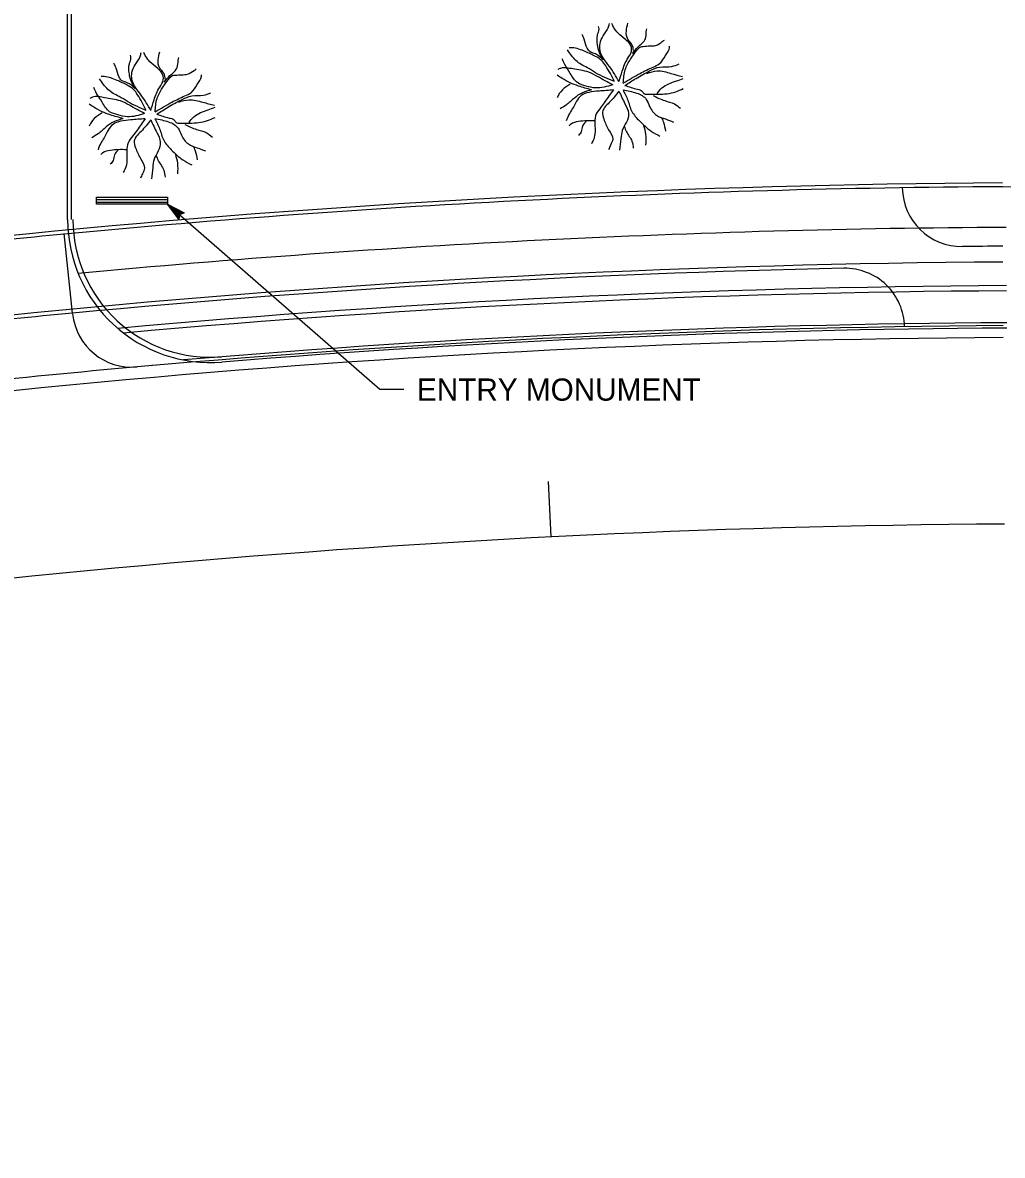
# Model space of a CAD drawing. Extents: x 6711323 to 6714641, y 1869258 to 1871224.
# Drawn here: x 6712585.3 to 6712708.8, y 1869509.9 to 1869652.6 of the extents above; entities that cross this region are included whole.
import ezdxf

# ---------------------------------------------------------------- set-up
doc = ezdxf.new("R2010")
doc.units = 0
for name, color, linetype in [('49 Planting', 7, 'Continuous'), ('Curb Gutter (21)', 7, 'Continuous'), ('Level 11', 7, 'Continuous'), ('Level 13', 7, 'Continuous'), ('Level 14', 7, 'Continuous'), ('Level 21', 7, 'Continuous'), ('Level 46', 7, 'Continuous'), ('Level 60', 7, 'Continuous'), ('Profile Grid (9)', 7, 'Continuous')]:
    doc.layers.add(name, color=color, linetype=linetype)

msp = doc.modelspace()

# ---------------------------------------------------------------- linework, layer by layer
at = {"layer": '49 Planting'}
for p, q in [((6712594.64, 1869629.99), (6712603.58, 1869629.99)), ((6712594.67, 1869630.32), (6712603.61, 1869630.32)), ((6712603.58, 1869629.74), (6712630.32, 1869606.44)), ((6712603.58, 1869629.74), (6712603.58, 1869629.74)), ((6712605.64, 1869628.63), (6712605.64, 1869628.63)), ((6712604.98, 1869627.86), (6712604.98, 1869627.86)), ((6712630.32, 1869606.44), (6712633.33, 1869606.44))]:
    msp.add_line(p, q, dxfattribs=at)
for points in [[(6712594.61, 1869630.62), (6712603.58, 1869630.62), (6712603.58, 1869629.74), (6712594.61, 1869629.74)], [(6712604.98, 1869627.86), (6712603.58, 1869629.74), (6712605.64, 1869628.63), (6712605.49, 1869628.58), (6712603.98, 1869629.39), (6712605.01, 1869628.01), (6712605.03, 1869628.17), (6712604.38, 1869629.05), (6712605.34, 1869628.53), (6712605.19, 1869628.48), (6712604.78, 1869628.71), (6712605.06, 1869628.32), (6712605.08, 1869628.45), (6712605.64, 1869628.63), (6712605.08, 1869628.45)]]:
    msp.add_lwpolyline(points, close=True, dxfattribs=at)
at = {"layer": 'Curb Gutter (21)'}
for p, q in [((6712590.97, 1869627.79), (6712590.97, 1869684.57)), ((6712591.47, 1869627.79), (6712591.47, 1869684.57))]:
    msp.add_line(p, q, dxfattribs=at)
for radius, start, end in [(18, 180, 184.1364), (17.33, 180.0001, 184.0883)]:
    msp.add_arc((6712608.97, 1869627.79), radius, start, end, dxfattribs=at)
at = {"layer": 'Level 11'}
for p, q in [((6712708.78, 1869631.94), (6712900.92, 1869633.18)), ((6712591.59, 1869616.01), (6712590.52, 1869626.04))]:
    msp.add_line(p, q, dxfattribs=at)
for centre, radius, start, end in [((6712717.46, 1868289.47), 1342.98, 90.36981, 110.14927), ((6712717.45, 1868289.47), 1342.5, 90.36992, 95.42473), ((6712703.67, 1869631.9), 7.5, 180.9083, 270.5882), ((6712717.45, 1868289.47), 1342.5, 95.42463, 96.70501), ((6712717.45, 1868289.47), 1335, 90.36992, 90.58819), ((6712717.46, 1868289.47), 1333, 90.36981, 110.14927), ((6712717.45, 1868289.47), 1332.5, 91.2326, 95.41993), ((6712688.95, 1869614.16), 7.5, 0.9083, 91.2326), ((6712717.45, 1868289.47), 1332.5, 95.41982, 96.70981), ((6712599.06, 1869616.7), 7.5, 186.0649, 275.0974), ((6712717.45, 1868289.47), 1325, 90.36992, 95.0974), ((6712717.45, 1868289.47), 1323.5, 90.36992, 110.14901)]:
    msp.add_arc(centre, radius, start, end, dxfattribs=at)
at = {"layer": 'Level 13'}
for centre, radius, start, end in [((6712717.45, 1868289.47), 1342.5, 90.36992, 95.42473), ((6712703.67, 1869631.9), 7.5, 180.9083, 270.5882), ((6712717.45, 1868289.47), 1335, 90.36992, 90.58819), ((6712717.45, 1868289.47), 1332.5, 91.2326, 95.41993), ((6712688.95, 1869614.16), 7.5, 0.9083, 91.2326), ((6712717.45, 1868289.47), 1325, 90.36992, 95.0974), ((6712717.45, 1868289.47), 1300, 90.36992, 110.14901)]:
    msp.add_arc(centre, radius, start, end, dxfattribs=at)
at = {"layer": 'Level 14'}
msp.add_lwpolyline([(6712651.52, 1869594.8), (6712651.87, 1869587.81)], dxfattribs=at)
at = {"layer": 'Level 21'}
msp.add_line((6712708.78, 1869631.94), (6712899.57, 1869633.17), dxfattribs=at)
for radius, start, end in [(1342.5, 95.42463, 96.70501), (1323.5, 90.36992, 110.14901), (1325, 95.0974, 97.03244), (1325, 95.01287, 95.01675)]:
    msp.add_arc((6712717.45, 1868289.47), radius, start, end, dxfattribs=at)
at = {"layer": 'Level 46'}
for centre, radius, start, end in [((6712608.97, 1869627.79), 18, 180, 274.6237), ((6712608.97, 1869627.79), 17.33, 180, 274.6237), ((6712716.96, 1868292.52), 1334.32, 90.33043, 95.36073), ((6712716.96, 1868292.52), 1326.98, 90.33043, 95.17418), ((6712716.96, 1868292.52), 1326.32, 90.33043, 95.14447), ((6712716.96, 1868292.52), 1322.3, 90.33043, 94.83264), ((6712716.96, 1868292.52), 1321.63, 90.33043, 94.6237)]:
    msp.add_arc(centre, radius, start, end, dxfattribs=at)
at = {"layer": 'Level 60'}
msp.add_line((6712591.59, 1869616.01), (6712590.52, 1869626.04), dxfattribs=at)
msp.add_arc((6712599.06, 1869616.7), 7.5, 186.0649, 275.0974, dxfattribs=at)
at = {"layer": 'Profile Grid (9)'}
for points in [[(6712660.48, 1869645.18), (6712659.25, 1869647.1), (6712658.08, 1869649.08), (6712658.08, 1869649.98), (6712658.47, 1869650.93), (6712659.12, 1869651.95), (6712659.25, 1869652.49)], [(6712660.48, 1869645.18), (6712660.87, 1869646.5), (6712661.58, 1869648.12), (6712662.04, 1869649.02), (6712661.84, 1869649.92), (6712661.32, 1869650.45), (6712660.35, 1869651.29), (6712659.83, 1869651.95), (6712659.57, 1869652.49)], [(6712662.29, 1869649.08), (6712662.1, 1869649.86), (6712661.97, 1869650.04), (6712661.58, 1869650.52), (6712661.39, 1869651.53), (6712661.58, 1869652.55)], [(6712658.47, 1869647.94), (6712657.5, 1869648.66), (6712656.79, 1869648.96), (6712656.46, 1869649.38), (6712656.07, 1869650.52), (6712655.82, 1869651.11)], [(6712658.47, 1869647.94), (6712657.95, 1869648.96), (6712657.76, 1869649.8), (6712657.76, 1869651.05), (6712657.95, 1869651.77), (6712657.89, 1869652.13)], [(6712662.17, 1869648.72), (6712662.88, 1869649.56), (6712663.79, 1869650.57), (6712663.91, 1869651.47), (6712663.98, 1869651.83)], [(6712661, 1869645), (6712661.26, 1869646.68), (6712661.91, 1869648), (6712662.68, 1869649.08), (6712663.2, 1869649.56), (6712663.53, 1869649.62), (6712664.37, 1869649.68), (6712665.08, 1869649.74), (6712665.92, 1869650.22), (6712666.18, 1869650.4)], [(6712661, 1869645), (6712663.12, 1869646.21), (6712664.76, 1869647.01), (6712665.54, 1869647.41), (6712666.32, 1869648.45), (6712666.83, 1869649.49), (6712666.83, 1869649.65)], [(6712599.47, 1869644.31), (6712598.95, 1869645.33), (6712598.75, 1869646.17), (6712598.75, 1869647.43), (6712598.95, 1869648.15), (6712598.88, 1869648.51)], [(6712601.47, 1869641.55), (6712600.24, 1869643.47), (6712599.08, 1869645.45), (6712599.08, 1869646.35), (6712599.47, 1869647.31), (6712600.11, 1869648.33), (6712600.24, 1869648.86)], [(6712601.47, 1869641.55), (6712601.86, 1869642.87), (6712602.58, 1869644.49), (6712603.03, 1869645.39), (6712602.84, 1869646.29), (6712602.32, 1869646.83), (6712601.35, 1869647.67), (6712600.83, 1869648.33), (6712600.57, 1869648.86)], [(6712603.29, 1869645.45), (6712603.09, 1869646.23), (6712602.97, 1869646.41), (6712602.58, 1869646.89), (6712602.38, 1869647.91), (6712602.58, 1869648.92)], [(6712603.16, 1869645.09), (6712603.87, 1869645.93), (6712604.78, 1869646.95), (6712604.91, 1869647.85), (6712604.97, 1869648.21)], [(6712659.9, 1869645.18), (6712657.51, 1869646.29), (6712656.48, 1869646.93), (6712655.7, 1869647.33), (6712654.49, 1869648.45), (6712653.98, 1869649.17)], [(6712659.9, 1869645.18), (6712658.8, 1869647.16), (6712658.28, 1869647.82), (6712657.5, 1869648.36), (6712656.2, 1869648.96), (6712654.58, 1869649.44), (6712654.2, 1869649.44)], [(6712599.47, 1869644.31), (6712598.49, 1869645.03), (6712597.78, 1869645.33), (6712597.46, 1869645.75), (6712597.07, 1869646.89), (6712596.81, 1869647.49)], [(6712601.99, 1869641.37), (6712602.25, 1869643.05), (6712602.9, 1869644.37), (6712603.68, 1869645.45), (6712604.2, 1869645.93), (6712604.52, 1869645.99), (6712605.36, 1869646.05), (6712606.08, 1869646.11), (6712606.92, 1869646.59), (6712607.18, 1869646.77)], [(6712659.67, 1869644.78), (6712657.77, 1869645.81), (6712656.65, 1869646.37), (6712655.62, 1869646.61), (6712654.67, 1869646.77), (6712653.11, 1869646.85), (6712652.77, 1869646.69)], [(6712659.67, 1869644.78), (6712657.51, 1869644.38), (6712656.31, 1869644.62), (6712655.27, 1869645.02), (6712654.32, 1869646.21), (6712653.63, 1869647.33), (6712653.29, 1869648.05)], [(6712661.22, 1869644.7), (6712662.61, 1869645.58), (6712664.33, 1869646.53), (6712665.63, 1869647.01), (6712667.09, 1869647.09), (6712668.04, 1869647.41)], [(6712600.89, 1869641.55), (6712598.51, 1869642.67), (6712597.47, 1869643.3), (6712596.7, 1869643.7), (6712595.49, 1869644.82), (6712594.97, 1869645.54)], [(6712600.89, 1869641.55), (6712599.79, 1869643.53), (6712599.27, 1869644.19), (6712598.49, 1869644.73), (6712597.2, 1869645.33), (6712595.58, 1869645.81), (6712595.19, 1869645.81)], [(6712601.99, 1869641.37), (6712604.12, 1869642.59), (6712605.76, 1869643.38), (6712606.53, 1869643.78), (6712607.31, 1869644.82), (6712607.83, 1869645.86), (6712607.83, 1869646.02)], [(6712657, 1869644.14), (6712655.36, 1869644.62), (6712654.32, 1869645.02), (6712653.29, 1869645.58), (6712652.68, 1869645.97)], [(6712663.99, 1869646.21), (6712665.28, 1869646.53), (6712667.01, 1869646.21), (6712668.47, 1869645.81)], [(6712665.28, 1869643.66), (6712665.88, 1869644.38), (6712667.7, 1869645.26), (6712668.56, 1869645.58)], [(6712600.67, 1869641.15), (6712598.51, 1869640.75), (6712597.3, 1869640.99), (6712596.27, 1869641.39), (6712595.32, 1869642.59), (6712594.63, 1869643.7), (6712594.28, 1869644.42)], [(6712654.32, 1869644.86), (6712653.8, 1869644.54), (6712652.94, 1869643.66), (6712652.68, 1869643.18)], [(6712657, 1869644.14), (6712655.79, 1869643.74), (6712654.84, 1869643.1), (6712653.8, 1869642.22), (6712653.03, 1869641.74)], [(6712659.76, 1869644.14), (6712657.95, 1869643.98), (6712656.65, 1869643.82), (6712655.7, 1869643.42), (6712655.1, 1869642.7), (6712654.58, 1869641.74), (6712654.15, 1869641.02), (6712653.8, 1869640.23)], [(6712659.76, 1869644.14), (6712659.24, 1869643.42), (6712658.2, 1869641.98), (6712657.6, 1869641.1), (6712657.43, 1869640.07), (6712657.34, 1869638.15), (6712657, 1869637.35)], [(6712660.45, 1869643.98), (6712659.24, 1869642.54), (6712658.64, 1869641.9), (6712658.38, 1869641.34), (6712658.55, 1869640.47), (6712659.15, 1869639.11), (6712659.67, 1869637.91), (6712659.41, 1869637.19), (6712659.15, 1869636.63)], [(6712660.45, 1869643.98), (6712661.22, 1869642.38), (6712661.66, 1869641.18), (6712661.4, 1869640.07), (6712660.88, 1869639.03), (6712660.71, 1869637.99), (6712660.53, 1869636.55)], [(6712660.97, 1869644.14), (6712661.57, 1869642.86), (6712662.09, 1869641.42), (6712663.04, 1869640.23), (6712664.5, 1869638.95), (6712665.63, 1869638.31)], [(6712660.97, 1869644.14), (6712662.69, 1869643.74), (6712663.38, 1869643.42), (6712663.9, 1869642.94), (6712664.33, 1869642.06), (6712665.19, 1869640.94), (6712666.32, 1869640.47), (6712667.35, 1869640.07)], [(6712661.22, 1869644.7), (6712662.78, 1869644.22), (6712663.38, 1869643.98), (6712663.64, 1869643.66), (6712664.16, 1869643.58), (6712665.37, 1869643.58), (6712667.61, 1869643.9), (6712668.56, 1869644.3)], [(6712600.67, 1869641.15), (6712598.77, 1869642.19), (6712597.65, 1869642.74), (6712596.61, 1869642.98), (6712595.66, 1869643.14), (6712594.11, 1869643.22), (6712593.76, 1869643.06)], [(6712602.22, 1869641.07), (6712603.6, 1869641.95), (6712605.33, 1869642.9), (6712606.62, 1869643.38), (6712608.09, 1869643.46), (6712609.04, 1869643.78)], [(6712604.98, 1869642.59), (6712606.27, 1869642.9), (6712608, 1869642.59), (6712609.47, 1869642.19)], [(6712664.76, 1869643.42), (6712666.23, 1869642.78), (6712667.44, 1869642.38), (6712668.21, 1869641.82)], [(6712597.99, 1869640.51), (6712596.35, 1869640.99), (6712595.32, 1869641.39), (6712594.28, 1869641.95), (6712593.68, 1869642.35)], [(6712595.32, 1869641.23), (6712594.8, 1869640.91), (6712593.94, 1869640.03), (6712593.68, 1869639.55)], [(6712602.22, 1869641.07), (6712603.77, 1869640.59), (6712604.38, 1869640.35), (6712604.64, 1869640.03), (6712605.15, 1869639.95), (6712606.36, 1869639.95), (6712608.6, 1869640.27), (6712609.55, 1869640.67)], [(6712606.27, 1869640.03), (6712606.88, 1869640.75), (6712608.69, 1869641.63), (6712609.55, 1869641.95)], [(6712597.99, 1869640.51), (6712596.78, 1869640.11), (6712595.83, 1869639.47), (6712594.8, 1869638.59), (6712594.02, 1869638.11)], [(6712600.75, 1869640.51), (6712598.94, 1869640.35), (6712597.65, 1869640.19), (6712596.7, 1869639.79), (6712596.09, 1869639.07), (6712595.58, 1869638.11), (6712595.14, 1869637.4), (6712594.8, 1869636.6)], [(6712600.75, 1869640.51), (6712600.23, 1869639.79), (6712599.2, 1869638.35), (6712598.6, 1869637.48), (6712598.42, 1869636.44), (6712598.34, 1869634.52), (6712597.99, 1869633.72)], [(6712601.44, 1869640.35), (6712600.23, 1869638.91), (6712599.63, 1869638.27), (6712599.37, 1869637.71), (6712599.54, 1869636.84), (6712600.15, 1869635.48), (6712600.67, 1869634.28), (6712600.41, 1869633.56), (6712600.15, 1869633)], [(6712601.44, 1869640.35), (6712602.22, 1869638.75), (6712602.65, 1869637.55), (6712602.39, 1869636.44), (6712601.87, 1869635.4), (6712601.7, 1869634.36), (6712601.53, 1869632.92)], [(6712601.96, 1869640.51), (6712602.56, 1869639.23), (6712603.08, 1869637.79), (6712604.03, 1869636.6), (6712605.5, 1869635.32), (6712606.62, 1869634.68)], [(6712601.96, 1869640.51), (6712603.69, 1869640.11), (6712604.38, 1869639.79), (6712604.89, 1869639.31), (6712605.33, 1869638.43), (6712606.19, 1869637.32), (6712607.31, 1869636.84), (6712608.35, 1869636.44)], [(6712605.76, 1869639.79), (6712607.22, 1869639.15), (6712608.43, 1869638.75), (6712609.21, 1869638.19)], [(6712657.43, 1869640.23), (6712655.36, 1869640.15), (6712654.41, 1869639.83), (6712654.15, 1869639.59)], [(6712656.31, 1869640.15), (6712655.88, 1869639.59), (6712655.7, 1869638.87), (6712655.36, 1869638.39)], [(6712663.55, 1869639.67), (6712663.81, 1869638.55), (6712663.81, 1869637.19)], [(6712665.8, 1869640.7), (6712666.06, 1869640.07), (6712666.32, 1869638.95)], [(6712661.14, 1869639.51), (6712661.4, 1869638.87), (6712662.09, 1869637.67), (6712662.26, 1869636.79)], [(6712606.79, 1869637.08), (6712607.05, 1869636.44), (6712607.31, 1869635.32)], [(6712598.42, 1869636.6), (6712596.35, 1869636.52), (6712595.4, 1869636.2), (6712595.14, 1869635.96)], [(6712597.3, 1869636.52), (6712596.87, 1869635.96), (6712596.7, 1869635.24), (6712596.35, 1869634.76)], [(6712602.13, 1869635.88), (6712602.39, 1869635.24), (6712603.08, 1869634.04), (6712603.25, 1869633.16)], [(6712604.55, 1869636.04), (6712604.81, 1869634.92), (6712604.81, 1869633.56)]]:
    msp.add_spline(points, degree=3, dxfattribs=at)

# ---------------------------------------------------------------- texts
at = {"layer": '49 Planting'}
msp.add_text('ENTRY MONUMENT', height=2.8, rotation=0, dxfattribs=at).set_placement((6712635, 1869604.98))

doc.saveas('drawing.dxf')
